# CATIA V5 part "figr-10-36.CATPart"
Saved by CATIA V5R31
Part number: Part1
Bounding box of the stored display mesh (mm): x -85.282 to 128.744, y -7.97 to 191.596, z 0 to 148.964
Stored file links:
  D:\PROJECTS\Project 2021\US EDITION\CATIA V5 6R 2021\Resources\Part Files\c10_catia_v5_6r2021_prt\c10_catia_v5_6r2021_prt\figr-10-36.CATPart
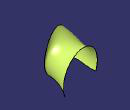
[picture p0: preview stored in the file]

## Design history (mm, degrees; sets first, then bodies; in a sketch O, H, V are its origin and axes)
Set1
  Sketch1 on xy-plane, origin (0, 0, 0), H (1, 0, 0), V (0, 1, 0)
    spline S1 through (-60, 0) (-70, 70) (-70, 170) (-80, 190)
  Sketch2 on yz-plane, origin (0, 0, 0), H (0, 1, 0), V (0, 0, 1)
    spline S1 through (0, 170) (100, 120) (180, 150)
  Sketch3 on xy-plane, origin (0, 0, 0), H (1, 0, 0), V (0, 1, 0)
    spline S1 through (70, 0) (70, 80) (120, 190)
  Sweep1: type Circle, Guide (Sketch1; Sketch2; Sketch3)
Body1 (main body)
